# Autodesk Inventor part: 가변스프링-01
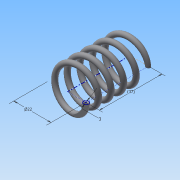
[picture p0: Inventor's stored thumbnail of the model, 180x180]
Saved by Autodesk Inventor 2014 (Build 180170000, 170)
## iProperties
Created: 2015-09
Part Number: 가변스프링-01
Material: 강철, 탄소
Document SubType Name: Modeling
Designer: study
Density: 7.87 g/cm^3
Appearance: 반연마
Mass: 18.7976 g
Surface Area: 32.4648 cm^2
Volume: 2.38851 cm^3
Author: study
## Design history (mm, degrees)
sketch "스케치1"
  geometry: L1 (0, 0)-(11, 0); L2 (11, 0)-(11, 29.043); L3 (11, 29.043)-(0, 29.043); L4 (0, 29.043)-(0, 0); C1 r 1.5 at (11, 0)
  constraints: 8 end point, 2 parallel, 1 centre point, 1 coincident, 1 horizontal, 1 perpendicular
  dimensions: "d0" = 22 diameter of L2 L4; "d1" = 3 diameter of C1; "d2" = 29.04259 distance of L1.end L2.end (derived)
feature "코일1" sketch "스케치1" pitch "d3" = 10; turns "d5" = 5; dims "d4" = 29.04259 (= d2), "d6" = 0, angle "d7" = 90 deg, angle "d8" = 90 deg, "d9" = 0, "d10" = 0
sketch "스케치2"
  geometry: L1 (-12.5, 0)-(-9.5, 0) reference; 1 further point
  constraints: 1 horizontal alignment
extrude "돌출1" cut sketch "스케치2" stored distance "d11" = 10; taper "d12" = 0 deg
node "작업 평면1"
sketch "스케치3"
  geometry: L1 (-9.5, 0)-(-12.5, 0) reference; 1 further point
  constraints: 1 horizontal alignment
extrude "돌출2" cut sketch "스케치3" stored distance "d14" = 10; taper "d15" = 0 deg
node "솔리드1"
node "절단 모서리 투영1"
node "절단 모서리 투영2"
other parameters: "d13" = 29.04259 (= d2)
